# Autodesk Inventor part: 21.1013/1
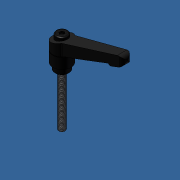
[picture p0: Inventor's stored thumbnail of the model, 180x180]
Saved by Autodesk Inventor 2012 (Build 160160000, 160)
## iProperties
Created: 2008-07
Part Number: 21.1013/1
Document SubType Name: Modeling
Mass: 81 g
Surface Area: 51.6674 cm^2
Volume: 13.455 cm^3
Density: 6.02005 g/cm^3
Description: SLIDE LOCK WITH M6X50 STUD
Material: Steel
Vendor: S
Dicke_ø: 1,000 mm
Bezeichnung: Klemmhebel M06x50 schwarz
Artikelnr: 211013/1
Lieferantennr: 72401
Zeichnungsnr: leer
MiniTec_ID: 211013/1
Teileart: K
Lieferant: MiniTec
Title: SLIDE LOCK WITH M6X50 STUD
Author: Oster
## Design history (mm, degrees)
feature "Basis1"
feature "Gewinde1" dims "d0" = 10, "d1" = 0
sketch "Sketch2"
  geometry: L1 (0, -1.732)-(-1.5, -0.866) reference; L2 (-1.5, -0.866)-(-1.5, 0.866) reference; L3 (-1.5, 0.866)-(0, 1.732) reference; L4 (0, 1.732)-(1.5, 0.866) reference; L5 (1.5, 0.866)-(1.5, -0.866) reference; L6 (1.5, -0.866)-(0, -1.732) reference; L7 (-2, -1.155)-(0, -2.309); L8 (0, -2.309)-(2, -1.155); L9 (2, -1.155)-(2, 1.155); L10 (2, 1.155)-(0, 2.309); L11 (0, 2.309)-(-2, 1.155); L12 (-2, 1.155)-(-2, -1.155)
  constraints: 12 end point, 5 other
  dimensions: "d2" = 4 distance between parallel lines of L12 L9
extrude "Extrusion1" cut sketch "Sketch2" distance "d3" = 2; taper "d4" = 0 deg
node "Volumenkörpern"
node "Oberflächenkörpern"
node "Volumenkörper1"
other parameters: "Länge" = 1 [user parameter], "Breite" = 1 [user parameter], "Dicke_ø" = 1 [user parameter]
